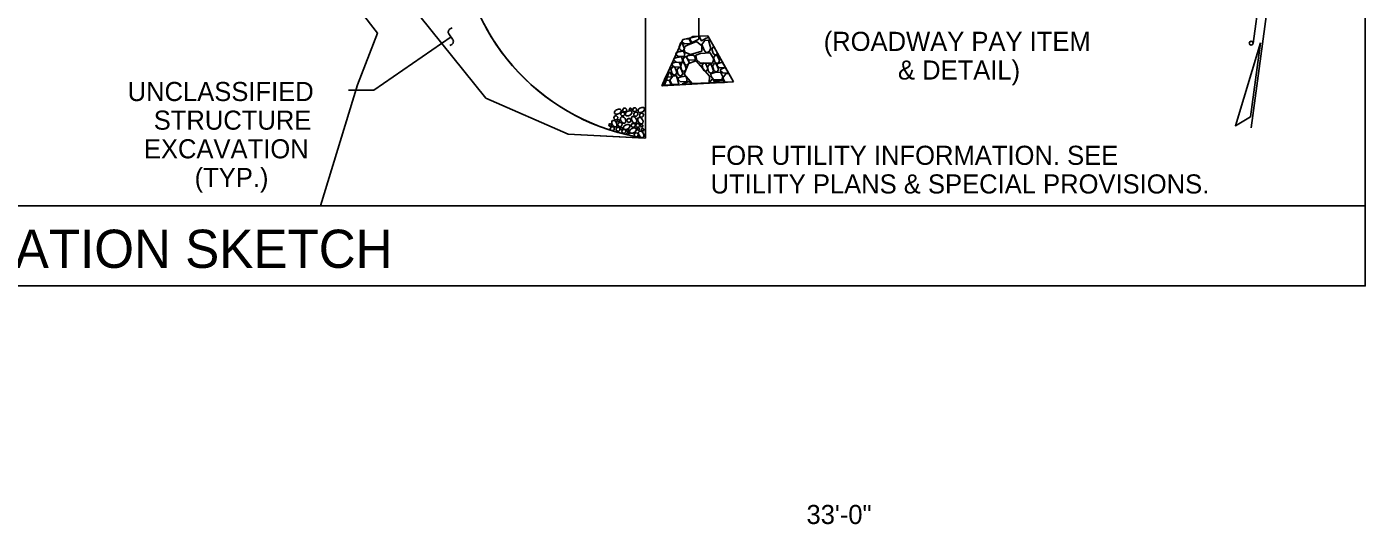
# Model space of a CAD drawing. Extents: x 471 to 2034, y -623 to 126.
# Drawn here: x 1574 to 1714, y -364.8 to -312.7 of the extents above; entities that cross this region are included whole.
import ezdxf

# ---------------------------------------------------------------- set-up
doc = ezdxf.new("R2010")
doc.units = 0
for name, color, linetype in [('Arrowhead Terminators CELL', 7, 'Continuous'), ('Default', 7, 'Continuous'), ('Dimension Lines', 7, 'Continuous'), ('Exist Hydro Stream or Body of Water', 7, 'Continuous'), ('Miscellaneous Lines CELL', 7, 'Continuous'), ('Plan Sheet CELL', 7, 'Continuous'), ('Sheet North Arrow CELL', 7, 'Continuous'), ('Sup Concrete Girder Lines', 7, 'Continuous'), ('Text', 7, 'Continuous'), ('Title Text', 7, 'Continuous')]:
    doc.layers.add(name, color=color, linetype=linetype)

msp = doc.modelspace()

# ---------------------------------------------------------------- linework, layer by layer
at = {"layer": 'Arrowhead Terminators CELL'}
for p, q in [((1618.54, -314.03), (1618.16, -313.49)), ((1618.3, -312.97), (1618.5, -312.87)), ((1618.25, -314.7), (1618.4, -314.63))]:
    msp.add_line(p, q, dxfattribs=at)
for centre, radius, start, end in [((1618.42, -313.28), 0.331, 110.3862, 218.6717), ((1618.26, -314.28), 0.373, 291.3177, 41.1166)]:
    msp.add_arc(centre, radius, start, end, dxfattribs=at)
at = {"layer": 'Default'}
for p, q in [((1615.12, -311.64), (1622.01, -320.21)), ((1642.43, -314.4), (1642.24, -314.84)), ((1642.84, -314.81), (1642.77, -315.15)), ((1643.68, -313.77), (1644.3, -313.74)), ((1644.3, -313.74), (1644.3, -313.74)), ((1644.4, -313.74), (1645.24, -313.7)), ((1645.31, -313.82), (1645.24, -313.7)), ((1645.87, -314.82), (1646.25, -315.51)), ((1641.91, -315.57), (1641.97, -315.43)), ((1640.69, -318.31), (1640.91, -317.81)), ((1641.01, -318.02), (1641.19, -317.51)), ((1642.48, -316.59), (1642.41, -316.91)), ((1647.09, -317.03), (1646.79, -316.49)), ((1647.43, -317.64), (1647.92, -318.52)), ((1640.42, -318.91), (1640.63, -318.43)), ((1640.89, -318.38), (1640.71, -318.86)), ((1642.23, -318.76), (1641.47, -318.8)), ((1643.55, -318.71), (1642.55, -318.75)), ((1645.4, -318.62), (1643.62, -318.7)), ((1645.97, -318.6), (1645.49, -318.62)), ((1646.29, -318.43), (1645.95, -318.45)), ((1646.12, -318.62), (1646.98, -318.58)), ((1647.03, -318.55), (1647.92, -318.51))]:
    msp.add_line(p, q, dxfattribs=at)
for points in [[(1642.56, -315.29), (1642.31, -315.12), (1642.24, -314.84)], [(1642.43, -314.4), (1642.57, -314.42), (1642.79, -314.98), (1642.74, -315.17), (1642.56, -315.29)], [(1642.62, -314.07), (1642.84, -314.05), (1643.29, -314.02), (1643.43, -314.31), (1643.44, -314.5), (1642.84, -314.54), (1642.53, -314.34), (1642.62, -314.07)], [(1642.84, -314.81), (1643.11, -314.67), (1644.07, -314.3), (1644.63, -314.75), (1644.61, -315.29), (1643.44, -315.66), (1642.85, -315.4), (1642.77, -315.15)], [(1644.31, -314.04), (1644.1, -314.13), (1643.62, -314.39), (1643.41, -314.11), (1643.4, -313.92), (1643.68, -313.77)], [(1644.3, -313.74), (1644.31, -314.04)], [(1645.31, -313.85), (1645.09, -313.95), (1644.58, -314.21), (1644.42, -313.91), (1644.4, -313.74)], [(1645.07, -315.47), (1644.87, -315.18), (1644.61, -314.61), (1644.93, -314.17), (1645.33, -314.14), (1645.58, -315.03), (1645.4, -315.33), (1645.07, -315.47)], [(1645.31, -313.82), (1645.31, -313.85)], [(1646.05, -315.71), (1645.8, -315.54), (1645.67, -315.06), (1645.87, -314.82)], [(1641.7, -316.05), (1641.99, -315.95), (1642.48, -315.88), (1642.61, -316.21), (1642.56, -316.48), (1641.92, -316.44), (1641.68, -316.24), (1641.7, -316.05)], [(1641.97, -315.43), (1642.22, -315.35), (1642.7, -315.28), (1642.83, -315.61), (1642.78, -315.87), (1642.14, -315.84), (1641.9, -315.64), (1641.91, -315.57)], [(1643, -316.78), (1642.77, -316.61), (1642.62, -316.13), (1642.84, -315.9), (1643.03, -315.89), (1643.28, -316.47), (1643.19, -316.69), (1643, -316.78)], [(1643.62, -318.7), (1642.79, -317.7), (1643.24, -316.58), (1644.02, -316.3), (1645.44, -317.92), (1645.4, -318.62)], [(1643.11, -315.76), (1643.33, -315.74), (1643.78, -315.7), (1643.92, -316), (1643.93, -316.19), (1643.33, -316.23), (1643.02, -316.03), (1643.11, -315.76)], [(1644.01, -315.7), (1644.49, -315.55), (1645.5, -315.48), (1645.89, -316.14), (1645.72, -316.56), (1644.48, -316.56), (1644.05, -316.17), (1644.01, -315.7)], [(1646.22, -316.6), (1645.98, -316.44), (1645.84, -315.95), (1646.05, -315.71), (1646.23, -315.74), (1646.46, -316.29), (1646.4, -316.48), (1646.22, -316.6)], [(1646.25, -315.51), (1646.23, -315.59), (1646.05, -315.71)], [(1640.91, -317.8), (1641.01, -318.05), (1640.96, -318.24), (1640.78, -318.36)], [(1641.19, -317.52), (1641.31, -317.51), (1641.45, -317.8), (1641.46, -317.99), (1641.01, -318.02)], [(1641.77, -317.82), (1641.53, -317.66), (1641.39, -317.18), (1641.59, -316.93), (1641.78, -316.96), (1642.01, -317.51), (1641.95, -317.7), (1641.77, -317.82)], [(1641.59, -316.52), (1641.81, -316.5), (1642.26, -316.46), (1642.4, -316.76), (1642.41, -316.95), (1641.81, -316.98), (1641.5, -316.78), (1641.59, -316.52)], [(1642.39, -317.91), (1642.15, -317.75), (1642.01, -317.27), (1642.21, -317.02), (1642.4, -317.05), (1642.63, -317.6), (1642.57, -317.79), (1642.39, -317.91)], [(1642.72, -317.44), (1642.51, -317.22), (1642.41, -316.91)], [(1642.48, -316.59), (1642.54, -316.51), (1642.76, -316.5), (1642.99, -317.12), (1642.9, -317.32), (1642.72, -317.44)], [(1645.01, -317.42), (1644.77, -317.25), (1644.64, -316.77), (1644.83, -316.52), (1645.02, -316.55), (1645.26, -317.1), (1645.19, -317.3), (1645.01, -317.42)], [(1645.55, -317.64), (1645.32, -317.43), (1645.22, -316.96), (1645.39, -316.71), (1645.61, -316.7), (1645.84, -317.33), (1645.74, -317.52), (1645.55, -317.64)], [(1645.58, -317.67), (1645.97, -317.52), (1646.57, -317.48), (1646.83, -317.99), (1646.7, -318.31), (1645.83, -318.27), (1645.59, -317.95), (1645.58, -317.67)], [(1646.12, -317.48), (1645.88, -317.32), (1645.74, -316.83), (1645.95, -316.59), (1646.13, -316.62), (1646.36, -317.17), (1646.3, -317.36), (1646.12, -317.48)], [(1647.09, -317.03), (1647.09, -317.05), (1646.45, -317.02), (1646.21, -316.81), (1646.23, -316.63)], [(1646.23, -316.63), (1646.53, -316.53), (1646.79, -316.49)], [(1647.41, -317.6), (1646.82, -317.57), (1646.58, -317.37), (1646.6, -317.18)], [(1646.6, -317.18), (1646.9, -317.08), (1647.1, -317.05)], [(1647.03, -318.55), (1646.82, -318.1), (1647.14, -317.66), (1647.43, -317.64)], [(1647.1, -317.05), (1647.1, -317.05), (1647.41, -317.6)], [(1640.48, -318.94), (1640.42, -318.91)], [(1640.63, -318.43), (1640.72, -318.63), (1640.66, -318.82), (1640.48, -318.94)], [(1640.78, -318.36), (1640.69, -318.3)], [(1640.89, -318.38), (1641.2, -318.35), (1641.33, -318.65), (1641.34, -318.84), (1640.74, -318.87), (1640.72, -318.86)], [(1641.47, -318.8), (1641.26, -318.34), (1641.58, -317.9), (1641.98, -317.87), (1642.23, -318.76)], [(1642.16, -318.09), (1642.45, -317.99), (1642.94, -317.92), (1643.07, -318.25), (1643.01, -318.52), (1642.37, -318.48), (1642.14, -318.28), (1642.16, -318.09)], [(1642.55, -318.75), (1642.6, -318.71), (1643.26, -318.47), (1643.55, -318.7)], [(1645.49, -318.62), (1645.46, -318.53), (1645.66, -318.28), (1645.85, -318.31), (1645.97, -318.6)], [(1645.95, -318.45), (1646.06, -318.31), (1646.25, -318.34), (1646.29, -318.43)], [(1646.11, -318.62), (1646.12, -318.55)], [(1646.12, -318.55), (1646.42, -318.45), (1646.9, -318.38), (1646.98, -318.58)], [(1622.01, -320.21), (1630.65, -323.98), (1638.73, -324.41)]]:
    msp.add_lwpolyline(points, dxfattribs=at)
at = {"layer": 'Dimension Lines'}
for p, q in [((1615.12, -311.64), (1622.01, -320.21)), ((1618.38, -313.8), (1610.29, -319.37)), ((1610.29, -319.37), (1607.64, -319.37))]:
    msp.add_line(p, q, dxfattribs=at)
msp.add_lwpolyline([(1622.01, -320.21), (1630.65, -323.98), (1638.65, -324.4)], dxfattribs=at)
msp.add_arc((1641.98, -301.9), 22.75, 184.9278, 261.5757, dxfattribs=at)
at = {"layer": 'Exist Hydro Stream or Body of Water'}
msp.add_lwpolyline([(1604.71, -331.48), (1608.61, -318.81), (1610.68, -313.4), (1608.87, -311.07), (1607.13, -304.33), (1608.39, -300.15)], dxfattribs=at)
at = {"layer": 'Miscellaneous Lines CELL'}
for points in [[(1635.68, -321.44), (1635.89, -321.36), (1636.08, -321.37), (1636.17, -321.46), (1636.17, -321.62), (1636.03, -321.79), (1635.81, -321.9), (1635.61, -321.9), (1635.5, -321.82), (1635.49, -321.66), (1635.58, -321.52), (1635.68, -321.43)], [(1636.13, -321.84), (1636.24, -321.68), (1636.42, -321.67), (1636.54, -321.8), (1636.53, -321.98), (1636.42, -322.07), (1636.24, -322.06), (1636.16, -321.98), (1636.13, -321.84)], [(1636.34, -321.42), (1636.45, -321.26), (1636.63, -321.25), (1636.75, -321.38), (1636.74, -321.56), (1636.63, -321.65), (1636.45, -321.64), (1636.37, -321.56), (1636.34, -321.42)], [(1636.81, -321.61), (1637.02, -321.53), (1637.22, -321.54), (1637.31, -321.63), (1637.31, -321.79), (1637.17, -321.96), (1636.95, -322.07), (1636.75, -322.07), (1636.64, -321.99), (1636.62, -321.83), (1636.72, -321.69), (1636.82, -321.6)], [(1637.02, -321.35), (1637.09, -321.26), (1637.19, -321.25), (1637.27, -321.33), (1637.26, -321.44), (1637.19, -321.49), (1637.09, -321.48), (1637.04, -321.44), (1637.02, -321.35)], [(1637.39, -321.39), (1637.5, -321.24), (1637.68, -321.23), (1637.8, -321.35), (1637.78, -321.53), (1637.67, -321.63), (1637.5, -321.61), (1637.41, -321.53), (1637.39, -321.39)], [(1637.49, -321.87), (1637.6, -321.71), (1637.78, -321.7), (1637.91, -321.83), (1637.89, -322.01), (1637.78, -322.1), (1637.6, -322.09), (1637.52, -322.01), (1637.49, -321.87)], [(1638.14, -321.27), (1638.35, -321.18), (1638.54, -321.2), (1638.63, -321.29), (1638.63, -321.44), (1638.49, -321.62), (1638.28, -321.73), (1638.07, -321.73), (1637.96, -321.65), (1637.95, -321.49), (1638.04, -321.35), (1638.15, -321.26)], [(1638.1, -321.97), (1638.22, -321.81), (1638.4, -321.8), (1638.52, -321.93), (1638.5, -322.11), (1638.39, -322.2), (1638.21, -322.19), (1638.13, -322.11), (1638.1, -321.97)], [(1634.9, -323.02), (1634.96, -322.92), (1635.07, -322.91), (1635.15, -322.99), (1635.14, -323.1), (1635.07, -323.16), (1634.96, -323.15), (1634.91, -323.1), (1634.9, -323.02)], [(1635.04, -323.38), (1635.16, -323.22), (1635.33, -323.21), (1635.46, -323.34), (1635.44, -323.52), (1635.33, -323.61), (1635.15, -323.6), (1635.07, -323.52), (1635.04, -323.38)], [(1635.66, -322.73), (1635.74, -322.94), (1635.73, -323.13), (1635.64, -323.23), (1635.48, -323.22), (1635.31, -323.08), (1635.2, -322.87), (1635.2, -322.67), (1635.28, -322.55), (1635.44, -322.54), (1635.58, -322.63), (1635.67, -322.74)], [(1635.41, -322.24), (1635.52, -322.08), (1635.7, -322.07), (1635.83, -322.2), (1635.81, -322.38), (1635.7, -322.47), (1635.52, -322.46), (1635.44, -322.38), (1635.41, -322.24)], [(1635.65, -323.42), (1635.76, -323.27), (1635.94, -323.26), (1636.06, -323.38), (1636.04, -323.56), (1635.93, -323.66), (1635.76, -323.64), (1635.67, -323.56), (1635.65, -323.42)], [(1635.79, -322.57), (1635.86, -322.47), (1635.97, -322.47), (1636.04, -322.54), (1636.03, -322.65), (1635.97, -322.71), (1635.86, -322.7), (1635.81, -322.65), (1635.79, -322.57)], [(1635.85, -322.95), (1635.96, -322.79), (1636.14, -322.78), (1636.27, -322.91), (1636.25, -323.09), (1636.14, -323.18), (1635.96, -323.17), (1635.88, -323.09), (1635.85, -322.95)], [(1636.11, -323.38), (1636.18, -323.28), (1636.28, -323.28), (1636.36, -323.36), (1636.35, -323.46), (1636.28, -323.52), (1636.17, -323.51), (1636.12, -323.46), (1636.11, -323.38)], [(1636.59, -322.35), (1636.67, -322.56), (1636.65, -322.76), (1636.57, -322.85), (1636.41, -322.84), (1636.23, -322.71), (1636.12, -322.49), (1636.12, -322.29), (1636.2, -322.17), (1636.36, -322.16), (1636.51, -322.26), (1636.59, -322.36)], [(1636.61, -323.05), (1636.82, -322.96), (1637.01, -322.98), (1637.1, -323.07), (1637.1, -323.22), (1636.96, -323.4), (1636.75, -323.51), (1636.55, -323.51), (1636.43, -323.43), (1636.42, -323.27), (1636.51, -323.12), (1636.62, -323.04)], [(1636.79, -322.51), (1636.9, -322.35), (1637.08, -322.34), (1637.2, -322.47), (1637.18, -322.65), (1637.07, -322.74), (1636.9, -322.73), (1636.81, -322.65), (1636.79, -322.51)], [(1637.26, -323.42), (1637.47, -323.34), (1637.66, -323.35), (1637.75, -323.44), (1637.75, -323.6), (1637.61, -323.77), (1637.4, -323.88), (1637.2, -323.89), (1637.08, -323.8), (1637.07, -323.64), (1637.16, -323.5), (1637.27, -323.41)], [(1637.24, -323.03), (1637.35, -322.87), (1637.53, -322.86), (1637.65, -322.99), (1637.63, -323.17), (1637.52, -323.26), (1637.35, -323.25), (1637.26, -323.17), (1637.24, -323.03)], [(1637.72, -322.33), (1637.81, -322.54), (1637.79, -322.73), (1637.7, -322.82), (1637.55, -322.82), (1637.37, -322.68), (1637.26, -322.46), (1637.26, -322.26), (1637.34, -322.15), (1637.5, -322.14), (1637.65, -322.23), (1637.73, -322.33)], [(1637.7, -323.04), (1637.81, -322.88), (1637.99, -322.87), (1638.11, -323), (1638.09, -323.18), (1637.98, -323.27), (1637.81, -323.26), (1637.72, -323.18), (1637.7, -323.04)], [(1637.86, -323.42), (1637.93, -323.33), (1638.03, -323.32), (1638.11, -323.4), (1638.1, -323.51), (1638.03, -323.56), (1637.93, -323.56), (1637.88, -323.51), (1637.86, -323.42)], [(1638.39, -322.43), (1638.47, -322.64), (1638.46, -322.83), (1638.37, -322.92), (1638.21, -322.92), (1638.03, -322.78), (1637.93, -322.56), (1637.92, -322.36), (1638.01, -322.25), (1638.17, -322.24), (1638.31, -322.33), (1638.39, -322.44)], [(1638.21, -323.09), (1638.27, -322.99), (1638.38, -322.99), (1638.46, -323.06), (1638.45, -323.17), (1638.38, -323.23), (1638.27, -323.22), (1638.22, -323.17), (1638.21, -323.09)], [(1638.3, -323.5), (1638.37, -323.41), (1638.48, -323.4), (1638.55, -323.48), (1638.54, -323.59), (1638.47, -323.64), (1638.37, -323.63), (1638.32, -323.59), (1638.3, -323.5)], [(1636.25, -323.67), (1636.36, -323.51), (1636.54, -323.5), (1636.66, -323.63), (1636.65, -323.81), (1636.54, -323.9), (1636.36, -323.89), (1636.28, -323.81), (1636.25, -323.67)], [(1636.76, -323.61), (1636.83, -323.51), (1636.94, -323.51), (1637.01, -323.58), (1637, -323.69), (1636.93, -323.75), (1636.83, -323.74), (1636.78, -323.69), (1636.76, -323.61)], [(1636.76, -323.9), (1636.83, -323.8), (1636.94, -323.79), (1637.01, -323.87), (1637, -323.98), (1636.93, -324.04), (1636.83, -324.03), (1636.78, -323.98), (1636.76, -323.9)], [(1637.54, -324.03), (1637.65, -323.87), (1637.83, -323.86), (1637.95, -323.99), (1637.93, -324.17), (1637.82, -324.26), (1637.65, -324.25), (1637.56, -324.17), (1637.54, -324.03)], [(1638.47, -323.86), (1638.55, -324.07), (1638.54, -324.26), (1638.45, -324.35), (1638.29, -324.35), (1638.12, -324.21), (1638.01, -324), (1638.01, -323.79), (1638.09, -323.68), (1638.25, -323.67), (1638.39, -323.76), (1638.48, -323.87)]]:
    msp.add_lwpolyline(points, dxfattribs=at)
at = {"layer": 'Plan Sheet CELL'}
msp.add_line((1473.05, -331.48), (1714.02, -331.48), dxfattribs=at)
msp.add_lwpolyline([(1473.05, -339.88), (1714.02, -339.88), (1714.02, -229.69)], dxfattribs=at)
at = {"layer": 'Sheet North Arrow CELL'}
for p, q in [((1702.08, -323.32), (1705.51, -298.2)), ((1703.01, -309.24), (1702.3, -314.48))]:
    msp.add_line(p, q, dxfattribs=at)
msp.add_lwpolyline([(1703.08, -314.44), (1700.45, -323.1), (1702.03, -322.17)], close=True, dxfattribs=at)
msp.add_circle((1702.09, -314.46), 0.207, dxfattribs=at)
at = {"layer": 'Sup Concrete Girder Lines'}
for p, q in [((1644.3, -274.99), (1644.3, -313.74)), ((1638.73, -303.85), (1638.73, -324.41)), ((1642.62, -314.07), (1640.42, -318.91)), ((1642.43, -314.4), (1642.24, -314.84)), ((1644.3, -313.74), (1642.62, -314.07)), ((1642.84, -314.81), (1642.77, -315.15)), ((1643.68, -313.77), (1644.3, -313.74)), ((1645.24, -313.7), (1644.3, -313.74)), ((1644.3, -313.74), (1644.3, -313.74)), ((1644.4, -313.74), (1645.24, -313.7)), ((1645.31, -313.82), (1645.24, -313.7)), ((1647.92, -318.51), (1645.24, -313.7)), ((1645.87, -314.82), (1646.25, -315.51)), ((1641.91, -315.57), (1641.97, -315.43)), ((1640.69, -318.31), (1640.91, -317.81)), ((1641.01, -318.02), (1641.19, -317.51)), ((1642.48, -316.59), (1642.41, -316.91)), ((1647.09, -317.03), (1646.79, -316.49)), ((1647.43, -317.64), (1647.92, -318.52)), ((1640.42, -318.91), (1640.63, -318.43)), ((1640.42, -318.91), (1647.92, -318.51)), ((1640.42, -318.91), (1647.92, -318.51)), ((1640.89, -318.38), (1640.71, -318.86)), ((1642.23, -318.76), (1641.47, -318.8)), ((1643.55, -318.71), (1642.55, -318.75)), ((1645.4, -318.62), (1643.62, -318.7)), ((1645.97, -318.6), (1645.49, -318.62)), ((1646.29, -318.43), (1645.95, -318.45)), ((1646.12, -318.62), (1646.98, -318.58)), ((1647.03, -318.55), (1647.92, -318.51))]:
    msp.add_line(p, q, dxfattribs=at)
for points in [[(1642.56, -315.29), (1642.31, -315.12), (1642.24, -314.84)], [(1642.43, -314.4), (1642.57, -314.42), (1642.79, -314.98), (1642.74, -315.17), (1642.56, -315.29)], [(1642.62, -314.07), (1642.84, -314.05), (1643.29, -314.02), (1643.43, -314.31), (1643.44, -314.5), (1642.84, -314.54), (1642.53, -314.34), (1642.62, -314.07)], [(1642.84, -314.81), (1643.11, -314.67), (1644.07, -314.3), (1644.63, -314.75), (1644.61, -315.29), (1643.44, -315.66), (1642.85, -315.4), (1642.77, -315.15)], [(1644.31, -314.04), (1644.1, -314.13), (1643.62, -314.39), (1643.41, -314.11), (1643.4, -313.92), (1643.68, -313.77)], [(1644.3, -313.74), (1644.31, -314.04)], [(1645.31, -313.85), (1645.09, -313.95), (1644.58, -314.21), (1644.42, -313.91), (1644.4, -313.74)], [(1645.07, -315.47), (1644.87, -315.18), (1644.61, -314.61), (1644.93, -314.17), (1645.33, -314.14), (1645.58, -315.03), (1645.4, -315.33), (1645.07, -315.47)], [(1645.31, -313.82), (1645.31, -313.85)], [(1646.05, -315.71), (1645.8, -315.54), (1645.67, -315.06), (1645.87, -314.82)], [(1641.7, -316.05), (1641.99, -315.95), (1642.48, -315.88), (1642.61, -316.21), (1642.56, -316.48), (1641.92, -316.44), (1641.68, -316.24), (1641.7, -316.05)], [(1641.97, -315.43), (1642.22, -315.35), (1642.7, -315.28), (1642.83, -315.61), (1642.78, -315.87), (1642.14, -315.84), (1641.9, -315.64), (1641.91, -315.57)], [(1643, -316.78), (1642.77, -316.61), (1642.62, -316.13), (1642.84, -315.9), (1643.03, -315.89), (1643.28, -316.47), (1643.19, -316.69), (1643, -316.78)], [(1643.62, -318.7), (1642.79, -317.7), (1643.24, -316.58), (1644.02, -316.3), (1645.44, -317.92), (1645.4, -318.62)], [(1643.11, -315.76), (1643.33, -315.74), (1643.78, -315.7), (1643.92, -316), (1643.93, -316.19), (1643.33, -316.23), (1643.02, -316.03), (1643.11, -315.76)], [(1644.01, -315.7), (1644.49, -315.55), (1645.5, -315.48), (1645.89, -316.14), (1645.72, -316.56), (1644.48, -316.56), (1644.05, -316.17), (1644.01, -315.7)], [(1646.22, -316.6), (1645.98, -316.44), (1645.84, -315.95), (1646.05, -315.71), (1646.23, -315.74), (1646.46, -316.29), (1646.4, -316.48), (1646.22, -316.6)], [(1646.25, -315.51), (1646.23, -315.59), (1646.05, -315.71)], [(1640.91, -317.8), (1641.01, -318.05), (1640.96, -318.24), (1640.78, -318.36)], [(1641.19, -317.52), (1641.31, -317.51), (1641.45, -317.8), (1641.46, -317.99), (1641.01, -318.02)], [(1641.77, -317.82), (1641.53, -317.66), (1641.39, -317.18), (1641.59, -316.93), (1641.78, -316.96), (1642.01, -317.51), (1641.95, -317.7), (1641.77, -317.82)], [(1641.59, -316.52), (1641.81, -316.5), (1642.26, -316.46), (1642.4, -316.76), (1642.41, -316.95), (1641.81, -316.98), (1641.5, -316.78), (1641.59, -316.52)], [(1642.39, -317.91), (1642.15, -317.75), (1642.01, -317.27), (1642.21, -317.02), (1642.4, -317.05), (1642.63, -317.6), (1642.57, -317.79), (1642.39, -317.91)], [(1642.72, -317.44), (1642.51, -317.22), (1642.41, -316.91)], [(1642.48, -316.59), (1642.54, -316.51), (1642.76, -316.5), (1642.99, -317.12), (1642.9, -317.32), (1642.72, -317.44)], [(1645.01, -317.42), (1644.77, -317.25), (1644.64, -316.77), (1644.83, -316.52), (1645.02, -316.55), (1645.26, -317.1), (1645.19, -317.3), (1645.01, -317.42)], [(1645.55, -317.64), (1645.32, -317.43), (1645.22, -316.96), (1645.39, -316.71), (1645.61, -316.7), (1645.84, -317.33), (1645.74, -317.52), (1645.55, -317.64)], [(1645.58, -317.67), (1645.97, -317.52), (1646.57, -317.48), (1646.83, -317.99), (1646.7, -318.31), (1645.83, -318.27), (1645.59, -317.95), (1645.58, -317.67)], [(1646.12, -317.48), (1645.88, -317.32), (1645.74, -316.83), (1645.95, -316.59), (1646.13, -316.62), (1646.36, -317.17), (1646.3, -317.36), (1646.12, -317.48)], [(1647.09, -317.03), (1647.09, -317.05), (1646.45, -317.02), (1646.21, -316.81), (1646.23, -316.63)], [(1646.23, -316.63), (1646.53, -316.53), (1646.79, -316.49)], [(1647.41, -317.6), (1646.82, -317.57), (1646.58, -317.37), (1646.6, -317.18)], [(1646.6, -317.18), (1646.9, -317.08), (1647.1, -317.05)], [(1647.03, -318.55), (1646.82, -318.1), (1647.14, -317.66), (1647.43, -317.64)], [(1647.1, -317.05), (1647.1, -317.05), (1647.41, -317.6)], [(1640.48, -318.94), (1640.42, -318.91)], [(1640.63, -318.43), (1640.72, -318.63), (1640.66, -318.82), (1640.48, -318.94)], [(1640.78, -318.36), (1640.69, -318.3)], [(1640.89, -318.38), (1641.2, -318.35), (1641.33, -318.65), (1641.34, -318.84), (1640.74, -318.87), (1640.72, -318.86)], [(1641.47, -318.8), (1641.26, -318.34), (1641.58, -317.9), (1641.98, -317.87), (1642.23, -318.76)], [(1642.16, -318.09), (1642.45, -317.99), (1642.94, -317.92), (1643.07, -318.25), (1643.01, -318.52), (1642.37, -318.48), (1642.14, -318.28), (1642.16, -318.09)], [(1642.55, -318.75), (1642.6, -318.71), (1643.26, -318.47), (1643.55, -318.7)], [(1645.49, -318.62), (1645.46, -318.53), (1645.66, -318.28), (1645.85, -318.31), (1645.97, -318.6)], [(1645.95, -318.45), (1646.06, -318.31), (1646.25, -318.34), (1646.29, -318.43)], [(1646.11, -318.62), (1646.12, -318.55)], [(1646.12, -318.55), (1646.42, -318.45), (1646.9, -318.38), (1646.98, -318.58)]]:
    msp.add_lwpolyline(points, dxfattribs=at)
for centre in [(1641.98, -301.89), (1641.98, -301.9)]:
    msp.add_arc(centre, 22.75, 184.9278, 261.7748, dxfattribs=at)

# ---------------------------------------------------------------- texts
at = {"layer": 'Text'}
for s, p in [('(ROADWAY PAY ITEM', (1657.37, -315.27)), ('& DETAIL)', (1665.14, -318.27)), ('UNCLASSIFIED', (1584.55, -320.52)), ('STRUCTURE', (1587.28, -323.52)), ('EXCAVATION', (1586.25, -326.52)), ('FOR UTILITY INFORMATION. SEE', (1645.54, -327.2)), ('(TYP.)', (1591.56, -329.52)), ('UTILITY PLANS & SPECIAL PROVISIONS.', (1645.54, -330.2)), ('33\'-0"', (1655.57, -364.81))]:
    msp.add_text(s, height=2, dxfattribs=at).set_placement(p)
at = {"layer": 'Title Text'}
msp.add_text('LOCATION SKETCH', height=4, dxfattribs=at).set_placement((1561.74, -337.99))

doc.saveas('drawing.dxf')
